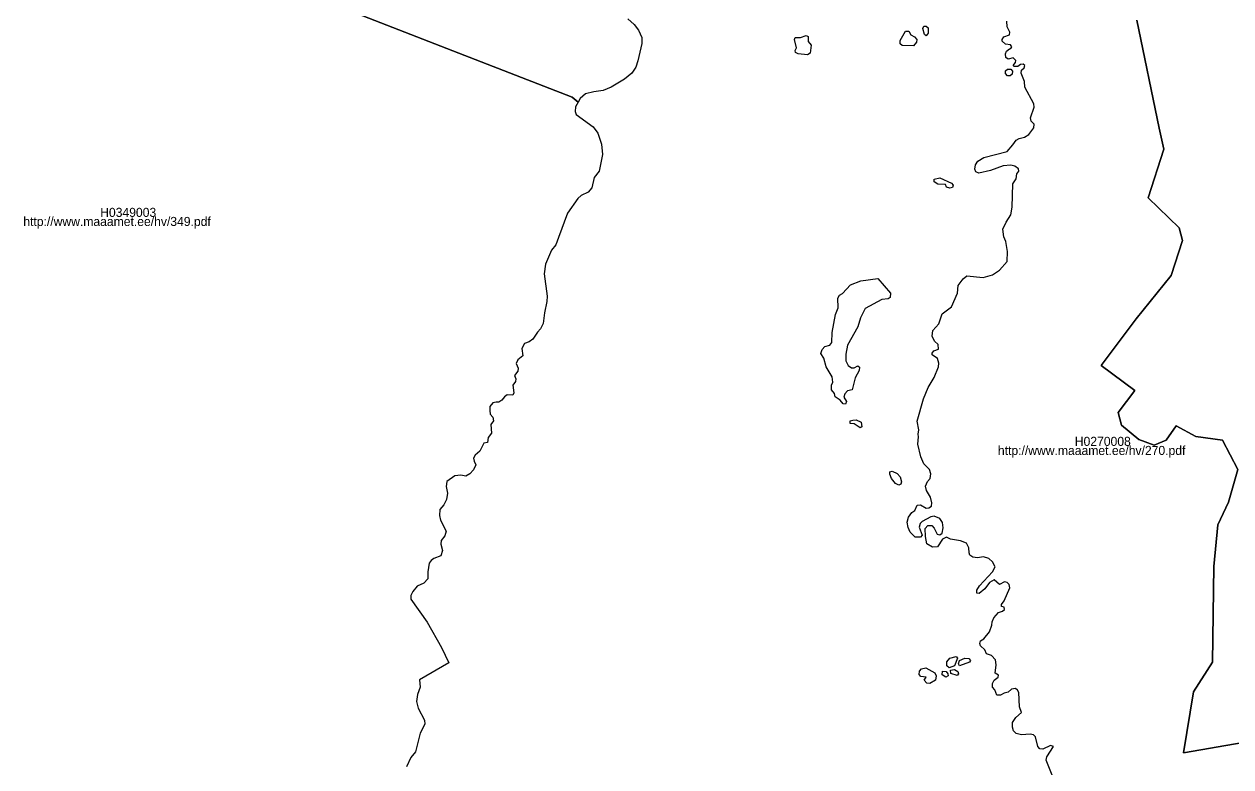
# Model space of a CAD drawing. Extents: x 369010 to 739155, y 6377141 to 6634081.
# Drawn here: x 411904 to 415228, y 6455316 to 6457361 of the extents above; entities that cross this region are included whole.
import ezdxf

# ---------------------------------------------------------------- set-up
doc = ezdxf.new("R2010")
doc.units = 0
for name, color, linetype in [('H_LINK', 7, 'Continuous'), ('H_PIIR', 7, 'Continuous'), ('H_TUNNUS', 7, 'Continuous')]:
    doc.layers.add(name, color=color, linetype=linetype)

msp = doc.modelspace()

# ---------------------------------------------------------------- linework, layer by layer
at = {"layer": 'H_PIIR'}
for points in [[(412753.94, 6457416.1046), (413084.98, 6457287.5547), (413413.37, 6457159.5447), (413429.7799, 6457146.0046), (413422.8599, 6457133.3546), (413421.6899, 6457120.7046), (413424.92, 6457111.8846), (413471.7, 6457077.7546), (413484.0499, 6457060.3946), (413494.34, 6457030.6746), (413496.99, 6457001.8446), (413487.5801, 6456956.2446), (413473.7501, 6456938.8846), (413467.2799, 6456910.3447), (413457.5701, 6456898.5746), (413438.15, 6456888.8647), (413429.3301, 6456880.9147), (413400.21, 6456840.6046), (413375.4999, 6456773.2246), (413368.1401, 6456752.9246), (413356.6701, 6456738.5046), (413339.9001, 6456699.9646), (413336.08, 6456673.1847), (413344.61, 6456611.6946), (413343.4201, 6456597.2746), (413336.9499, 6456566.3847), (413333.4199, 6456536.9647), (413326.36, 6456521.9547), (413317.54, 6456513.1346), (413304.89, 6456493.4146), (413294.8801, 6456486.3546), (413281.94, 6456481.0547), (413274.88, 6456467.5246), (413277.82, 6456447.2246), (413264, 6456436.6347), (413258.9899, 6456426.3446), (413264.58, 6456413.6946), (413263.6901, 6456405.4547), (413254.87, 6456393.3947), (413257.8099, 6456383.9847), (413257.51, 6456376.9146), (413249.8701, 6456366.9146), (413252.8101, 6456345.4347), (413249.57, 6456339.5547), (413234.57, 6456339.8446), (413226.92, 6456334.5546), (413219.8601, 6456325.1347), (413211.33, 6456319.8346), (413203.97, 6456320.4246), (413194.85, 6456318.3647), (413186.9099, 6456307.7747), (413186.3199, 6456296.8847), (413187.21, 6456286.5947), (413194.5601, 6456278.9447), (413196.91, 6456268.9346), (413189.2701, 6456258.3447), (413191.33, 6456234.8246), (413182.21, 6456223.0547), (413180.45, 6456208.9346), (413170.1499, 6456207.4647), (413159.2701, 6456185.3946), (413146.6201, 6456174.5047), (413141.9099, 6456165.6746), (413143.6699, 6456157.1446), (413148.09, 6456147.7346), (413141.9099, 6456133.9046), (413131.6101, 6456122.4246), (413120.14, 6456116.5446), (413106.9, 6456119.1947), (413090.43, 6456117.1346), (413068.0699, 6456101.2447), (413066.3099, 6456087.7046), (413069.8401, 6456069.1646), (413067.4799, 6456051.8147), (413059.84, 6456037.0946), (413049.25, 6456024.1546), (413048.07, 6456008.2646), (413050.42, 6455995.3146), (413066.01, 6455965.0146), (413063.07, 6455952.3647), (413052.78, 6455939.4046), (413051.3099, 6455929.4047), (413056.0201, 6455911.1546), (413051.3099, 6455897.3346), (413032.48, 6455889.9746), (413025.13, 6455884.0946), (413019.83, 6455877.0246), (413016.01, 6455853.1947), (413016.01, 6455833.4847), (413005.1199, 6455821.7146), (412986.3, 6455813.1846), (412974.23, 6455799.0547), (412969.23, 6455787.5846), (412968.9401, 6455777.8746), (413013.9501, 6455714.3346), (413053.6599, 6455644.3047), (413073.67, 6455602.2347), (412993.0599, 6455555.4447), (412995.12, 6455535.7346), (412987.18, 6455514.8446), (412984.82, 6455496.0147), (412989.24, 6455477.1846), (413006.2999, 6455444.8147), (413007.77, 6455433.6347), (412995.13, 6455408.3247), (412981.89, 6455357.4246), (412968.65, 6455341.5347), (412957.18, 6455315.6446)], [(413566.43, 6457375.1847), (413584.3699, 6457359.5947), (413596.43, 6457344.5846), (413605.55, 6457324.2846), (413605.8501, 6457307.8147), (413594.67, 6457259.5646), (413588.79, 6457241.9047), (413577.91, 6457225.7246), (413557.8999, 6457209.5446), (413520.83, 6457186.8846), (413498.91, 6457177.7746), (413473.0199, 6457174.8346), (413450.0801, 6457168.9546), (413435.6601, 6457156.0047), (413429.7799, 6457146.0046), (413413.37, 6457159.5447), (413084.98, 6457287.5547), (412753.94, 6457416.1046)], [(414741.69, 6455278.8146), (414719.63, 6455334.4247), (414720.96, 6455343.2447), (414739.4899, 6455371.7846), (414731.5501, 6455375.0247), (414709.78, 6455364.4347), (414702.1301, 6455365.9046), (414696.54, 6455372.0847), (414689.77, 6455398.5647), (414684.1799, 6455404.1546), (414675.36, 6455406.2146), (414651.53, 6455403.8647), (414636.8199, 6455407.9746), (414629.17, 6455415.3347), (414626.82, 6455424.7546), (414626.82, 6455437.6947), (414635.6499, 6455452.1147), (414651.53, 6455465.3546), (414646.2401, 6455480.9447), (414644.4701, 6455520.3747), (414640.3499, 6455526.8446), (414634.47, 6455531.2647), (414623.5899, 6455529.4947), (414615.0501, 6455521.2546), (414603.58, 6455518.6147), (414593.29, 6455513.3147), (414583.58, 6455513.3147), (414578.28, 6455528.3147), (414571.52, 6455535.0846), (414571.2201, 6455545.0947), (414576.52, 6455554.8047), (414587.11, 6455562.4547), (414587.7, 6455568.3346), (414578.87, 6455574.2146), (414581.81, 6455596.8746), (414580.05, 6455610.9947), (414569.16, 6455622.4747), (414555.34, 6455627.1846), (414550.63, 6455637.7746), (414538.8601, 6455649.2446), (414536.79, 6455655.1346), (414538.56, 6455662.7847), (414547.9699, 6455668.6747), (414563.27, 6455687.2046), (414570.0401, 6455706.3346), (414570.33, 6455715.4546), (414575.33, 6455726.6346), (414587.98, 6455741.0546), (414599.16, 6455744.2847), (414604.75, 6455749.2847), (414604.16, 6455755.1747), (414596.81, 6455757.2346), (414596.22, 6455762.5247), (414603.57, 6455773.1247), (414618.87, 6455808.4246), (414617.4001, 6455818.1347), (414612.1001, 6455823.7247), (414605.04, 6455824.9047), (414590.92, 6455817.8446), (414576.2099, 6455830.7947), (414563.27, 6455823.4346), (414550.3299, 6455806.0746), (414534.44, 6455793.4246), (414528.56, 6455793.7147), (414528.26, 6455801.9547), (414535.62, 6455814.6047), (414571.8001, 6455852.5747), (414578.5699, 6455866.3947), (414571.51, 6455880.5246), (414561.2099, 6455889.3446), (414546.7899, 6455894.3546), (414530.03, 6455891.1146), (414517.67, 6455893.4646), (414508.8501, 6455899.0546), (414507.0799, 6455905.2347), (414506.4899, 6455919.0647), (414500.31, 6455932.0146), (414483.55, 6455938.4847), (414455.89, 6455942.6047), (414444.7099, 6455947.9047), (414434.12, 6455942.6047), (414420.0001, 6455921.9947), (414406.1701, 6455920.5246), (414390.5801, 6455929.9447), (414386.76, 6455949.9446), (414385.8799, 6455972.0147), (414393.5301, 6455980.8447), (414404.12, 6455979.9546), (414410.88, 6455973.1947), (414419.12, 6455956.4247), (414426.7699, 6455954.3646), (414432.95, 6455959.6546), (414435.5901, 6455973.7847), (414433.8301, 6455989.0846), (414426.47, 6455999.6747), (414410.59, 6456006.1447), (414401.4699, 6456004.6746), (414377.64, 6455991.7247), (414372.0499, 6455986.1346), (414369.4, 6455975.5447), (414377.64, 6455954.0647), (414372.93, 6455948.1846), (414358.2201, 6455948.1846), (414344.4001, 6455962.0146), (414339.0999, 6455975.2546), (414336.45, 6455989.3747), (414340.2799, 6456003.7947), (414349.69, 6456016.4447), (414357.34, 6456021.4446), (414364.4, 6456036.7447), (414372.93, 6456037.3347), (414388.52, 6456028.2146), (414395.88, 6456029.3846), (414403.2301, 6456033.8047), (414404.12, 6456042.6346), (414400.8799, 6456058.5247), (414389.9901, 6456076.4647), (414387.0499, 6456089.1247), (414392.64, 6456101.7747), (414399.99, 6456109.4247), (414402.0499, 6456122.3646), (414397.64, 6456134.1347), (414382.05, 6456150.6146), (414374.4001, 6456169.1446), (414365.87, 6456204.1646), (414367.63, 6456224.4646), (414366.3001, 6456231.8147), (414368.6501, 6456243.5846), (414364.24, 6456268.0047), (414381.8901, 6456329.2047), (414394.5399, 6456360.6946), (414410.7199, 6456388.3446), (414423.08, 6456417.1846), (414423.9699, 6456427.4846), (414420.14, 6456440.1347), (414405.73, 6456450.1346), (414405.4299, 6456455.1446), (414409.5499, 6456461.0246), (414422.5, 6456466.0247), (414422.1999, 6456478.9746), (414411.3201, 6456487.5046), (414405.73, 6456501.6247), (414407.1999, 6456517.5146), (414423.3799, 6456535.4646), (414432.79, 6456563.4147), (414458.97, 6456582.5447), (414475.15, 6456620.2046), (414477.21, 6456641.3847), (414490.74, 6456659.9247), (414500.45, 6456667.8647), (414545.46, 6456663.4546), (414571.34, 6456670.8147), (414590.46, 6456683.7546), (414611.64, 6456707.2946), (414612.82, 6456734.3647), (414608.7001, 6456762.0247), (414602.52, 6456775.5546), (414600.17, 6456796.4446), (414609.58, 6456815.5747), (414622.23, 6456836.1646), (414625.4701, 6456857.0547), (414627.24, 6456920.9046), (414636.3601, 6456934.7346), (414638.7101, 6456948.2647), (414644.2999, 6456955.9147), (414643.12, 6456962.3946), (414632.8299, 6456969.4546), (414622.24, 6456972.1047), (414601.35, 6456970.9247), (414566.34, 6456957.9746), (414533.84, 6456950.6247), (414525.9, 6456953.8646), (414523.2501, 6456961.5147), (414524.4301, 6456972.9846), (414531.49, 6456983.5747), (414547.3699, 6456993.5846), (414611.8, 6457010.3546), (414627.98, 6457028.3046), (414637.1, 6457041.5446), (414644.74, 6457045.6546), (414659.4601, 6457049.1947), (414671.81, 6457057.1346), (414685.64, 6457075.6746), (414686.5199, 6457085.3846), (414677.7, 6457093.9146), (414675.93, 6457102.7446), (414686.5199, 6457132.4547), (414685.05, 6457141.2846), (414660.34, 6457186.8846), (414659.4601, 6457202.4846), (414650.93, 6457226.0246), (414651.2199, 6457234.2546), (414658.58, 6457240.1446), (414660.34, 6457246.9146), (414656.22, 6457250.1447), (414649.16, 6457249.2646), (414641.22, 6457244.2647), (414631.2201, 6457243.9646), (414628.57, 6457247.2047), (414635.34, 6457254.8546), (414635.92, 6457261.0347), (414628.8601, 6457268.3846), (414615.0401, 6457264.5647), (414608.27, 6457269.2746), (414607.09, 6457278.9847), (414610.04, 6457286.6346), (414617.9801, 6457292.8047), (414621.7999, 6457293.3947), (414624.7499, 6457298.4046), (414621.2199, 6457303.4046), (414607.3899, 6457305.4647), (414598.56, 6457313.9946), (414597.98, 6457318.4046), (414602.3901, 6457325.7647), (414617.9801, 6457331.3547), (414619.45, 6457338.4147), (414611.5099, 6457353.7146), (414610.9199, 6457369.3046)], [(415686.72, 6455456.7101), (415097.9901, 6455354.6001), (415125.6801, 6455522.4801), (415177.35, 6455603.8201), (415181.22, 6455867.83), (415192.29, 6455982.06), (415221.82, 6456044.36), (415247.66, 6456134.36), (415205.2401, 6456215.3901), (415131.4201, 6456225.7699), (415077.9, 6456255.1899), (415050.22, 6456215.3901), (415017, 6456201.5401), (414974.5501, 6456217.1201), (414926.5701, 6456256.9199), (414917.3401, 6456291.5299), (414963.4801, 6456352.1099), (414871.2001, 6456421.3299), (414967.17, 6456549.3999), (415063.42, 6456668.3801), (415094.79, 6456765.3001), (415085.56, 6456799.9101), (415000.67, 6456882.9801), (415044.03, 6457017.01), (415030.3799, 6457074.34), (414969.58, 6457372.02)], [(414969.58, 6457372.02), (415030.3799, 6457074.34), (415044.03, 6457017.01), (415000.67, 6456882.9801), (415085.56, 6456799.9101), (415094.79, 6456765.3001), (415063.42, 6456668.3801), (414967.17, 6456549.3999), (414871.2001, 6456421.3299), (414963.4801, 6456352.1099), (414917.3401, 6456291.5299), (414926.5701, 6456256.9199), (414974.5501, 6456217.1201), (415017, 6456201.5401), (415050.22, 6456215.3901), (415077.9, 6456255.1899), (415131.4201, 6456225.7699), (415205.2401, 6456215.3901), (415247.66, 6456134.36), (415221.82, 6456044.36), (415192.29, 6455982.06), (415181.22, 6455867.83), (415177.35, 6455603.8201), (415125.6801, 6455522.4801), (415097.9901, 6455354.6001), (415686.72, 6455456.7101)]]:
    msp.add_lwpolyline(points, dxfattribs=at)
for points in [[(414362.1084, 6457310.7931), (414353.5022, 6457300.6973), (414322.3875, 6457301.8559), (414317.2568, 6457306.6555), (414317.2568, 6457316.0893), (414331.9867, 6457341.9079), (414341.4205, 6457341.9079), (414346.2201, 6457330.9847), (414356.4813, 6457325.6885), (414363.267, 6457318.0752)], [(414394.3817, 6457335.7843), (414388.7546, 6457328.171), (414384.1204, 6457331.9776), (414379.652, 6457349.0246), (414382.6309, 6457354.8172), (414388.7546, 6457354.8172), (414394.0508, 6457351.0106)], [(414068.8354, 6457281.3335), (414062.0496, 6457276.6993), (414036.5621, 6457278.6853), (414028.6179, 6457282.4919), (414027.6249, 6457287.7881), (414031.2659, 6457295.2357), (414026.3008, 6457318.4063), (414027.9558, 6457324.0335), (414042.6858, 6457324.1989), (414058.0775, 6457329.6606), (414063.5392, 6457326.6815), (414063.3737, 6457313.1102), (414072.1454, 6457302.518)], [(414625.9218, 6457222.7449), (414620.6256, 6457218.4419), (414613.0126, 6457218.6074), (414607.0544, 6457224.5656), (414607.7164, 6457231.8477), (414612.6815, 6457236.6473), (414622.1152, 6457236.9783), (414627.0804, 6457231.0202)], [(414461.5763, 6456911.101), (414454.2941, 6456909.2805), (414444.8604, 6456911.5976), (414441.8815, 6456919.5417), (414420.6969, 6456920.5347), (414411.2632, 6456926.6584), (414411.2632, 6456934.106), (414426.324, 6456937.2506), (414458.9283, 6456923.1827), (414462.7349, 6456917.059)], [(414182.7022, 6456414.7545), (414190.6464, 6456414.589), (414200.0801, 6456419.8852), (414205.0452, 6456416.244), (414204.2177, 6456407.1412), (414193.2944, 6456386.7844), (414184.8536, 6456353.6836), (414171.7789, 6456351.0354), (414164.6622, 6456342.7603), (414161.6831, 6456333.3266), (414169.1307, 6456321.9067), (414166.9793, 6456314.79), (414160.5245, 6456315.1211), (414152.2494, 6456325.3824), (414138.5126, 6456334.8161), (414136.0299, 6456343.5878), (414128.2514, 6456353.8491), (414127.5893, 6456366.9238), (414131.7269, 6456374.8679), (414129.4098, 6456389.7633), (414112.8594, 6456417.4025), (414106.5703, 6456441.0695), (414098.295, 6456453.979), (414102.4327, 6456465.0677), (414109.7149, 6456473.6739), (414123.2862, 6456476.8185), (414128.9133, 6456484.5972), (414129.5753, 6456511.5743), (414139.009, 6456561.5565), (414146.7877, 6456580.093), (414145.2982, 6456606.5735), (414149.9323, 6456614.8488), (414158.704, 6456618.9864), (414180.7161, 6456643.481), (414208.3552, 6456653.7422), (414255.6893, 6456660.5279), (414290.1142, 6456619.9794), (414289.7831, 6456608.3942), (414284.156, 6456604.5876), (414266.6126, 6456602.7671), (414220.9335, 6456578.1069), (414207.5277, 6456552.4538), (414200.9076, 6456527.7936), (414171.9444, 6456477.1495), (414167.1448, 6456452.1583), (414167.4757, 6456433.6219), (414173.5994, 6456421.0436)], [(414211.9964, 6456252.3951), (414207.3622, 6456249.7471), (414190.3153, 6456260.6702), (414179.061, 6456261.4979), (414179.7231, 6456268.6145), (414186.3432, 6456270.6005), (414196.108, 6456270.9314), (414209.3482, 6456265.1388)], [(414318.5809, 6456093.8423), (414313.1193, 6456091.1941), (414304.1821, 6456096.1593), (414293.0933, 6456109.7306), (414288.2937, 6456121.4814), (414288.9556, 6456128.5981), (414295.0793, 6456130.0876), (414309.3126, 6456123.3019), (414316.9259, 6456114.3648), (414320.4014, 6456100.6278)], [(414466.707, 6455593.8546), (414451.8116, 6455588.8895), (414445.8536, 6455593.8546), (414445.8536, 6455604.7779), (414453.7977, 6455615.3702), (414471.5066, 6455619.8387), (414475.3132, 6455615.0391)], [(414507.9174, 6455604.2815), (414480.2783, 6455593.6891), (414477.6303, 6455599.4817), (414480.9403, 6455608.419), (414495.6702, 6455615.0391), (414506.4279, 6455614.5427), (414510.8965, 6455608.419)], [(414414.2421, 6455554.2992), (414398.6849, 6455545.0309), (414391.0716, 6455546.0241), (414383.4584, 6455554.2992), (414388.4236, 6455563.0709), (414374.5212, 6455564.2295), (414369.5562, 6455570.353), (414370.2182, 6455578.9592), (414376.3417, 6455586.0759), (414388.0925, 6455588.8895), (414412.2562, 6455575.1528), (414416.0628, 6455566.2155)], [(414449.1636, 6455566.5466), (414443.0399, 6455563.0709), (414432.6132, 6455568.8636), (414434.1028, 6455579.4558), (414444.1984, 6455578.6283), (414448.5016, 6455571.8426)], [(414478.2923, 6455571.8426), (414474.6512, 6455567.2084), (414456.7767, 6455573.3321), (414455.6182, 6455581.9383), (414466.5415, 6455584.2554), (414476.4716, 6455577.9663)]]:
    msp.add_lwpolyline(points, close=True, dxfattribs=at)

# ---------------------------------------------------------------- texts
at = {"layer": 'H_LINK'}
for s, p in [('http://www.maaamet.ee/hv/349.pdf', (411901.2247, 6456805.0246)), ('http://www.maaamet.ee/hv/270.pdf', (414586.4707, 6456174.5436))]:
    msp.add_text(s, height=25, rotation=360, dxfattribs=at).set_placement(p)
at = {"layer": 'H_TUNNUS'}
for s, p in [('H0349003', (412113.0793, 6456830.0246)), ('H0270008', (414798.3252, 6456199.5436))]:
    msp.add_text(s, height=25, rotation=360, dxfattribs=at).set_placement(p)

doc.saveas('drawing.dxf')
